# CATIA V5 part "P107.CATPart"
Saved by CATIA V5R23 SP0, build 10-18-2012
Part number: P107
Definition: Axe Came
Description: Axe De Came Rotation Plateau
Bounding box of the stored display mesh (mm): x 0 to 130, y -8 to 8, z -8 to 8
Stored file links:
  C:\wamp\www\COURS\CONCEPTION GMP1\TITRE 02-SEMESTRE 2\03-TP7-PRESSE MECANIQUE\eleve\P107.CATPart
  C:\wamp\www\COURS\CONCEPTION GMP1\TITRE 02-SEMESTRE 2\03-TP7-PRESSE MECANIQUE\eleve\05-LICP-T02-E-S08-P109.CATPart
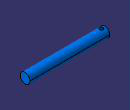
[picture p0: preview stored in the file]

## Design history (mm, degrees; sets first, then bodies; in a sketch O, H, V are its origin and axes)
Set1
  Plane1: stored without definition
  DatumCurve1
  Plane2: stored without definition
  DatumCurve2
  Plane3: stored without definition
  Plane4: stored without definition
  DatumCurve3
  DatumCurve4
  DatumSurface1
  DatumCurve5 to DatumCurve8
  Plane5: stored without definition
  Plane6: stored without definition
  DatumCurve9
  Plane7: stored without definition
  DatumCurve10 to DatumCurve12
  Plane8: stored without definition
  DatumCurve13
  DatumCurve14
Body1 (main body)
  Sketch1 on yz-plane, origin (0, 0, 0), H (0, 1, 0), V (0, 0, 1)
    circle A1 centre (0, 0) radius 8
    radius A1 = 8
  Pad1: profile Sketch1, direction (1, 0, 0), length 130
  Sketch2 on xy-plane, origin (0, 0, 0), H (1, 0, 0), V (0, 1, 0)
    circle A1 centre (6, 0) radius 3
    point P1 (6, 0)
    radius A1 = 3
    distance P1 V = 6
    coincidence: P1 H
  Pocket1: profile Sketch2, direction (0, 0, -1), length 15, mirrored extent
